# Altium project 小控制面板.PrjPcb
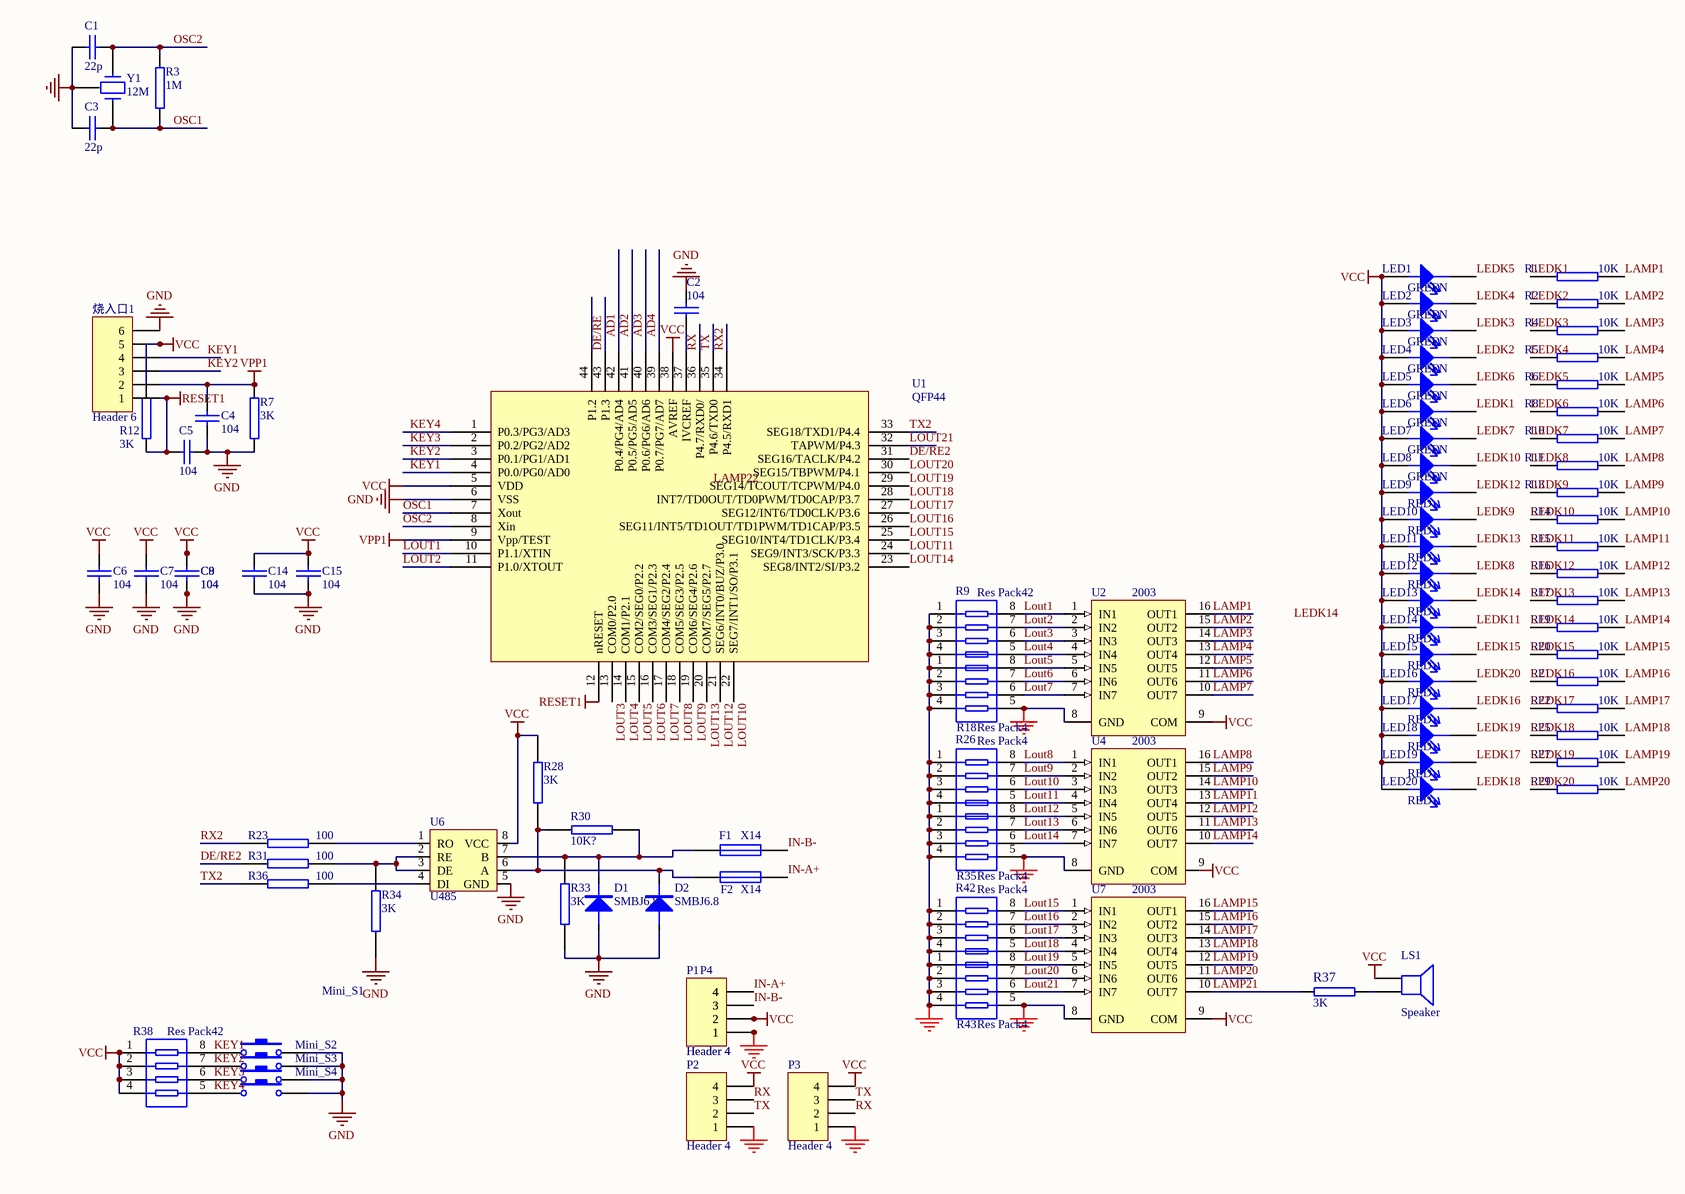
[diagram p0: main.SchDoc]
1 sheet, 89 parts. Net scope: global (net labels, ports and power ports of the same name join across sheets).
Board file: main.PcbDoc

## Sheet main.SchDoc
size A2

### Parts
C1  22p  [0805]
C2  104  [0805]
C3  22p  [0805]
C4  104  [0805]
C5  104  [0805]
C6  104  [E6.5MM*10]
C7  104  [0805]
C8  104  [0805]
C9  104  [0805]
C14  104  [E6.5MM*10]
C15  104  [0805]
D1  SMBJ6.8  [SMBJ_SMT]
D2  SMBJ6.8  [SMBJ_SMT]
F1  X14  [PPTC_SMT]
F2  X14  [PPTC_SMT]
LED1  GREEN  [PLED10*10]
LED2  GREEN  [PLED10*10]
LED3  GREEN  [PLED10*10]
LED4  GREEN  [PLED10*10]
LED5  GREEN  [PLED10*10]
LED6  GREEN  [PLED10*10]
LED7  GREEN  [PLED10*10]
LED8  GREEN  [PLED10*10]
LED9  RED  [PLED10*10]
LED10  RED  [PLED10*10]
LED11  RED  [PLED10*10]
LED12  RED  [PLED10*10]
LED13  RED  [PLED10*10]
LED14  RED  [PLED10*10]
LED15  RED  [PLED10*10]
LED16  RED  [PLED10*10]
LED17  RED  [PLED10*10]
LED18  RED  [PLED10*10]
LED19  RED  [PLED10*10]
LED20  RED  [PLED10*10]
LS1  Speaker  [SPK]
Mini_S1  (no value)  [KEYL]
Mini_S2  (no value)  [KEYL]
Mini_S3  (no value)  [KEYL]
Mini_S4  (no value)  [KEYL]
P1  Header 4  [PL4X]
P2  Header 4  [HDR1X4]
P3  Header 4  [HDR1X4]
P4  Header 4  [C3-4L]
R1  10K  [0805]
R2  10K  [0805]
R3  1M  [0805]
R4  10K  [0805]
R5  10K  [0805]
R6  10K  [0805]
R7  3K  [0805]
R8  10K  [0805]
R9  Res Pack42  [RES4]
R10  10K  [0805]
R11  10K  [0805]
R12  3K  [0805]
R13  10K  [0805]
R14  10K  [0805]
R15  10K  [0805]
R16  10K  [0805]
R17  10K  [0805]
R18  Res Pack4  [RES4]
R19  10K  [0805]
R20  10K  [0805]
R21  10K  [0805]
R22  10K  [0805]
R23  100  [0805]
R25  10K  [0805]
R26  Res Pack4  [RES4]
R27  10K  [0805]
R28  3K  [0805]
R29  10K  [0805]
R30  10K?  [0805]
R31  100  [0805]
R33  3K  [0805]
R34  3K  [0805]
R35  Res Pack4  [RES4]
R36  100  [0805]
R37  3K  [0805]
R38  Res Pack42  [RES4]
R42  Res Pack4  [RES4]
R43  Res Pack4  [RES4]
U1  QFP44  [QFP44]
U2  2003  [SO_16]
U4  2003  [SO_16]
U6  U485  [SOP8]
U7  2003  [SO_16]
Y1  12M  [X3]
烧入口1  Header 6  [HDR1X6]

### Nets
GND: C1.2 C2.1 C3.2 C4.2 C5.2 C6.2 C7.2 C8.2 C9.2 C14.2 C15.2 D1.A D2.A Mini_S1.2 Mini_S2.2 Mini_S3.2 Mini_S4.2 P1.1 P2.1 P3.1 P4.1 R7.2 R9.1 R9.2 R9.3 R9.4 R18.1 R18.2 R18.3 R18.4 R18.5 R26.1 R26.2 R26.3 R26.4 R33.1 R34.1 R35.1 R35.2 R35.3 R35.4 R35.5 R42.1 R42.2 R42.3 R42.4 R43.1 R43.2 R43.3 R43.4 R43.5 U1.6(VSS) U2.8(GND) U4.8(GND) U6.5(GND) U7.8(GND) Y1.3 烧入口1.6
RESET1: C5.1 R12.1 U1.12(nRESET) 烧入口1.1
VCC: C6.1 C7.1 C8.1 C9.1 C14.1 C15.1 LED1.A LED2.A LED3.A LED4.A LED5.A LED6.A LED7.A LED8.A LED9.A LED10.A LED11.A LED12.A LED13.A LED14.A LED15.A LED16.A LED17.A LED18.A LED19.A LED20.A LS1.1 P1.2 P2.4 P3.4 P4.2 R12.2 R28.1 R38.1 R38.2 R38.3 R38.4 U1.5(VDD) U1.38(AVREF) U2.9(COM) U4.9(COM) U6.8(VCC) U7.9(COM) 烧入口1.5
VPP1: C4.1 R7.1 U1.9(Vpp/TEST) 烧入口1.2
AD1: U1.42(P0.4/PG4/AD4)
AD2: U1.41(P0.5/PG5/AD5)
AD3: U1.40(P0.6/PG6/AD6)
AD4: U1.39(P0.7/PG7/AD7)
DE/RE: U1.43(P1.3)
DE/RE2: R31.2 U1.31(SEG16/TACLK/P4.2)
IN-A+: F2.1 P1.4 P4.4
IN-B-: F1.1 P1.3 P4.3
KEY1: Mini_S1.1 R38.8 U1.4(P0.0/PG0/AD0) 烧入口1.4
KEY2: Mini_S2.1 R38.7 U1.3(P0.1/PG1/AD1) 烧入口1.3
KEY3: Mini_S3.1 R38.6 U1.2(P0.2/PG2/AD2)
KEY4: Mini_S4.1 R38.5 U1.1(P0.3/PG3/AD3)
LAMP1: R1.2 U2.16(OUT1)
LAMP2: R2.2 U2.15(OUT2)
LAMP3: R4.2 U2.14(OUT3)
LAMP4: R5.2 U2.13(OUT4)
LAMP5: R6.2 U2.12(OUT5)
LAMP6: R8.2 U2.11(OUT6)
LAMP7: R10.2 U2.10(OUT7)
LAMP8: R11.2 U4.16(OUT1)
LAMP9: R13.2 U4.15(OUT2)
LAMP10: R14.2 U4.14(OUT3)
LAMP11: R15.2 U4.13(OUT4)
LAMP12: R16.2 U4.12(OUT5)
LAMP13: R17.2 U4.11(OUT6)
LAMP14: R19.2 U4.10(OUT7)
LAMP15: R20.2 U7.16(OUT1)
LAMP16: R21.2 U7.15(OUT2)
LAMP17: R22.2 U7.14(OUT3)
LAMP18: R25.2 U7.13(OUT4)
LAMP19: R27.2 U7.12(OUT5)
LAMP20: R29.2 U7.11(OUT6)
LAMP21: R37.1 U7.10(OUT7)
LEDK1: LED6.K R1.1
LEDK2: LED4.K R2.1
LEDK3: LED3.K R4.1
LEDK4: LED2.K R5.1
LEDK5: LED1.K R6.1
LEDK6: LED5.K R8.1
LEDK7: LED7.K R10.1
LEDK8: LED12.K R11.1
LEDK9: LED10.K R13.1
LEDK10: LED8.K R14.1
LEDK11: LED14.K R15.1
LEDK12: LED9.K R16.1
LEDK13: LED11.K R17.1
LEDK14: LED13.K R19.1
LEDK15: LED15.K R20.1
LEDK16: LED17.K R21.1
LEDK17: LED19.K R22.1
LEDK18: LED20.K R25.1
LEDK19: LED18.K R27.1
LEDK20: LED16.K R29.1
Lout1: R9.8 U1.10(P1.1/XTIN) U2.1(IN1)
Lout2: R9.7 U1.11(P1.0/XTOUT) U2.2(IN2)
Lout3: R9.6 U1.13(COM0/P2.0) U2.3(IN3)
Lout4: R9.5 U1.14(COM1/P2.1) U2.4(IN4)
Lout5: R18.8 U1.15(COM2/SEG0/P2.2) U2.5(IN5)
Lout6: R18.7 U1.16(COM3/SEG1/P2.3) U2.6(IN6)
Lout7: R18.6 U1.17(COM4/SEG2/P2.4) U2.7(IN7)
Lout8: R26.8 U1.18(COM5/SEG3/P2.5) U4.1(IN1)
Lout9: R26.7 U1.19(COM6/SEG4/P2.6) U4.2(IN2)
Lout10: R26.6 U1.22(SEG7/INT1/SO/P3.1) U4.3(IN3)
Lout11: R26.5 U1.24(SEG9/INT3/SCK/P3.3) U4.4(IN4)
Lout12: R35.8 U1.21(SEG6/INT0/BUZ/P3.0) U4.5(IN5)
Lout13: R35.7 U1.20(COM7/SEG5/P2.7) U4.6(IN6)
Lout14: R35.6 U1.23(SEG8/INT2/SI/P3.2) U4.7(IN7)
Lout15: R42.8 U1.25(SEG10/INT4/TD1CLK/P3.4) U7.1(IN1)
Lout16: R42.7 U1.26(SEG11/INT5/TD1OUT/TD1PWM/TD1CAP/P3.5) U7.2(IN2)
Lout17: R42.6 U1.27(SEG12/INT6/TD0CLK/P3.6) U7.3(IN3)
Lout18: R42.5 U1.28(INT7/TD0OUT/TD0PWM/TD0CAP/P3.7) U7.4(IN4)
Lout19: R43.8 U1.29(SEG14/TCOUT/TCPWM/P4.0) U7.5(IN5)
Lout20: R43.7 U1.30(SEG15/TBPWM/P4.1) U7.6(IN6)
Lout21: R43.6 U1.32(TAPWM/P4.3) U7.7(IN7)
OSC1: C3.1 R3.2 U1.7(Xout) Y1.2
OSC2: C1.1 R3.1 U1.8(Xin) Y1.1
RX: P2.3 P3.2 U1.36(P4.7/RXD0/)
RX2: R23.2 U1.34(P4.5/RXD1)
TX: P2.2 P3.3 U1.35(P4.6/TXD0)
TX2: R36.2 U1.33(SEG18/TXD1/P4.4)
NetC2_2: C2.2 U1.37(IVCREF)
NetD1_K: D1.K F1.2 R30.1 R33.2 U6.7(B)
NetD2_K: D2.K F2.2 R28.2 R30.2 U6.6(A)
NetLS1_2: LS1.2 R37.2
NetR23_1: R23.1 U6.1(RO)
NetR31_1: R31.1 R34.2 U6.2(RE) U6.3(DE)
NetR36_1: R36.1 U6.4(DI)

Not connected (* = marked no-connect by the designer): U1 44(P1.2)

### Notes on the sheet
- Labels drawn without touching a wire or pin: LAMP22, LEDK14

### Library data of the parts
C1-C9 C14 C15 = CAP: Capacitor
D1 D2 = DIODE
F1 F2 = Fuse 1: Fuse
LED1-LED20 = LED: Zener Diode
LS1 = Speaker: Loudspeaker
Mini_S1-Mini_S4 = SW-PB: Switch
P1-P4 = Header 4: Header, 4-Pin
R1-R8 R10-R17 R19-R23 R25 R27-R31 R33 R34 R36 R37 = RES2
R9 R18 R26 R35 R38 R42 R43 = Res Pack4: Isolated Resistor Network
U1 = S3F84UA
U2 U4 U7 = ULN2003A: High-Voltage, High-Current Darlington Array
Y1 = CRYSTAL2
烧入口1 = Header 6: Header, 6-Pin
